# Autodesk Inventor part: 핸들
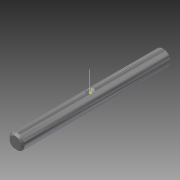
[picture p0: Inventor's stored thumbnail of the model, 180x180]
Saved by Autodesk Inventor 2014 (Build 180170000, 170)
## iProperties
Created: 2019-04
Part Number: 핸들
Material: 스테인리스강
Document SubType Name: Modeling
Designer: mduedu
Density: 1 g/cm^3
Appearance: 반광택
Author: mduedu
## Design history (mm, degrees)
sketch "스케치1"
  geometry: C1 r 4 at (0, 0); 1 further point
  constraints: 1 centre point, 1 coincident
  dimensions: "d0" = 8 diameter of C1
extrude "돌출1" new body sketch "스케치1" stored distance "d1" = 80; taper "d2" = 0 deg
chamfer "모따기1" distance "d3" = 1; stored, may be unused: second distance "d4" = 2, angle "d5" = 45 deg
sketch "스케치2"
  geometry: L1 (-39, 4)-(39, 4) reference; L2 (0, 4)-(0, 2); L3 (0, 2)-(2, 4); L4 (0, 4)-(2, 4); 1 further point
  constraints: 6 end point, 2 perpendicular, 1 midpoint, 1 point on line
  dimensions: "d6" = 4 diameter of L3.end L2; "d8" = 45 deg angle of L3 L2
revolve "회전1" sketch "스케치2" stored, may be unused: angle "d10" = 90 deg
node "작업점1"
  node "작업축1"
  node "작업 평면1"
node "작업점2"
  node "작업축2"
node "솔리드1"
